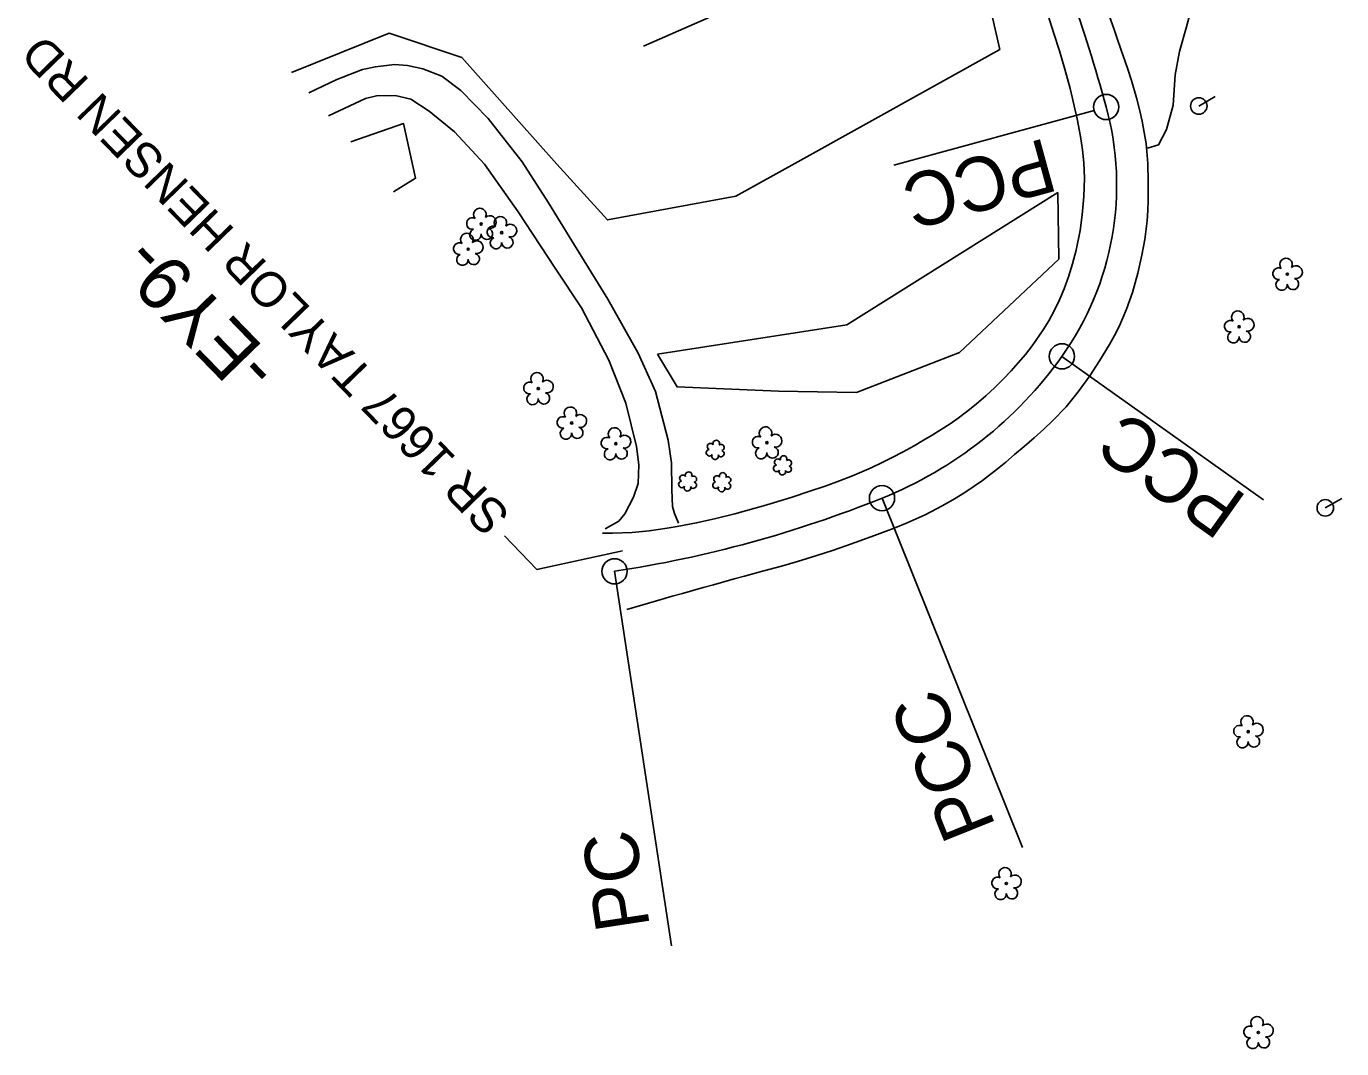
# Model space of a CAD drawing. Extents: x 473158 to 477500, y 500738 to 505114.
# Drawn here: x 475161.7 to 475552.3, y 502010.9 to 502314.3 of the extents above; entities that cross this region are included whole.
import ezdxf

# ---------------------------------------------------------------- set-up
doc = ezdxf.new("R2010")
doc.units = 0
for name, color, linetype in [('Exist Horizontal Alignment', 7, 'Continuous'), ('Exist Horizontal Alignment Direction Label', 7, 'Continuous'), ('Exist Roads EOP', 7, 'Continuous'), ('Exist Roads EOP Leader', 7, 'Continuous'), ('Exist Roads EOP Text', 7, 'Continuous'), ('Exist Roads Soil', 7, 'Continuous'), ('Exist Utilities Power Pole CELL', 7, 'Continuous'), ('Exist Vegetation Shrub CELL', 7, 'Continuous'), ('Exist Vegetation Tree CELL', 7, 'Continuous'), ('Exist Vegetation Woods Line', 7, 'Continuous')]:
    doc.layers.add(name, color=color, linetype=linetype)

msp = doc.modelspace()

# ---------------------------------------------------------------- linework, layer by layer
at = {"layer": 'Exist Horizontal Alignment'}
for p, q in [((475454.89, 502356.7), (475344.98, 502308.44)), ((475478.74, 502289.39), (475419.35, 502273.12)), ((475529.02, 502173.8), (475469.22, 502216.37)), ((475457.54, 502070.57), (475415.8, 502174.28)), ((475353.33, 502041.37), (475336.39, 502152.56))]:
    msp.add_line(p, q, dxfattribs=at)
for centre in [(475482.35, 502290.39), (475469.22, 502216.37), (475415.8, 502174.28), (475336.39, 502152.56)]:
    msp.add_circle(centre, 3.75, dxfattribs=at)
for centre, radius, start, end in [((475007.6, 502160.31), 492.25, 15.3225, 23.7048), ((475397.79, 502267.22), 87.68, 324.5533, 15.3225), ((475370.61, 502286.57), 121.05, 291.9237, 324.5533), ((475282.71, 502504.97), 356.47, 278.6615, 291.9237)]:
    msp.add_arc(centre, radius, start, end, dxfattribs=at)
at = {"layer": 'Exist Roads EOP'}
for points in [[(475332.79, 502163.87), (475335.79, 502163.86), (475341.59, 502164.06), (475346.7, 502164.55), (475351.96, 502165.34), (475354.93, 502165.84), (475360.73, 502166.92), (475366.45, 502168.2), (475372.12, 502169.6), (475377.76, 502171.18), (475380.66, 502172.03), (475383.62, 502172.9), (475389.12, 502174.6), (475394.08, 502176.22), (475398.91, 502177.87), (475403.19, 502179.42), (475407.05, 502180.92), (475412.54, 502183.27), (475415.86, 502184.85), (475418.85, 502186.37), (475422.04, 502188.02), (475425.3, 502189.83), (475428.1, 502191.47), (475430.66, 502192.99), (475433.36, 502194.64), (475436.03, 502196.38), (475438.45, 502198.07), (475440.9, 502199.92), (475443.73, 502202.2), (475446.59, 502204.66), (475449.25, 502207.14), (475451.76, 502209.63), (475454.16, 502212.09), (475456.26, 502214.45), (475458.35, 502216.94), (475460.38, 502219.51), (475463.68, 502224.27), (475465.31, 502226.94), (475466.93, 502229.86), (475468.5, 502233.13), (475469.87, 502236.43), (475471.15, 502239.99), (475472.35, 502243.79), (475473.46, 502247.92), (475474.62, 502253.73), (475475.27, 502258.35), (475475.73, 502263.83), (475475.89, 502269.28), (475475.73, 502273.83), (475475.35, 502277.69), (475474.76, 502281.61), (475473.73, 502286.84), (475473.07, 502289.82), (475472.36, 502292.89), (475471.62, 502295.87), (475470.09, 502301.58), (475468.48, 502307.06), (475466.86, 502312.17), (475465.09, 502317.5)], [(475483.2, 502317.55), (475484.78, 502313.06), (475485.51, 502310.98), (475486.82, 502307.23), (475488.68, 502301.86), (475489.91, 502298.21), (475491.39, 502293.07), (475492.26, 502289.66), (475493.03, 502286.2), (475493.68, 502282.8), (475494.18, 502279.58), (475494.71, 502273.62), (475494.86, 502268.2), (475494.83, 502262.63), (475494.72, 502259.63), (475494.51, 502256.57), (475493.81, 502251.03), (475492.93, 502246.42), (475491.79, 502241.07), (475490.21, 502235.31), (475488.43, 502230.34), (475486.24, 502225.22), (475484.87, 502222.55), (475483.35, 502219.9), (475480.39, 502215.07), (475477.48, 502210.59), (475474.03, 502205.79), (475470.5, 502201.39), (475466.43, 502197.19), (475463.83, 502194.78), (475460.95, 502192.21), (475457.99, 502189.63), (475455.18, 502187.21), (475452.54, 502184.97), (475450.09, 502182.96), (475445.59, 502179.51), (475443.13, 502177.81), (475440.09, 502175.81), (475436.82, 502173.79), (475433.68, 502172.01), (475428.6, 502169.35), (475423.31, 502166.94), (475419.45, 502165.38), (475414.4, 502163.5), (475409.24, 502161.65), (475405.07, 502160.16), (475401.06, 502158.78), (475396.4, 502157.23), (475390.68, 502155.43), (475385.93, 502154.14), (475380.31, 502152.62), (475374.95, 502151.14), (475371.93, 502150.29), (475368.88, 502149.45), (475365.81, 502148.59), (475362.7, 502147.72), (475359.6, 502146.86), (475356.53, 502145.99), (475353.49, 502145.14), (475350.49, 502144.28), (475344.8, 502142.65), (475339.99, 502141.25)]]:
    msp.add_lwpolyline(points, dxfattribs=at)
at = {"layer": 'Exist Roads EOP Leader'}
msp.add_lwpolyline([(475338.72, 502158.6), (475313.34, 502153.09), (475303.69, 502163.12)], dxfattribs=at)
at = {"layer": 'Exist Roads Soil'}
for points in [[(475476.71, 502335.29), (475479.28, 502331.91), (475481.59, 502329.05), (475482.85, 502327.84), (475484.2, 502327.08), (475485.85, 502326.42), (475487.62, 502326.45), (475489.07, 502326.88), (475490.2, 502327.82), (475492.83, 502331.2), (475496.1, 502339.6), (475499.62, 502353.76), (475501.41, 502361.15), (475505.61, 502359.29), (475517.48, 502352.5), (475509.78, 502327.56), (475506.16, 502314.15), (475504.1, 502306.86), (475502.79, 502299.95), (475502.25, 502290.94), (475500.28, 502283.72), (475497.91, 502279.11), (475494.63, 502278.17)], [(475245.62, 502294.54), (475253.91, 502298.54), (475261.56, 502301.52), (475265.37, 502302.33), (475271.04, 502303.02), (475274.91, 502302.7), (475279.45, 502301.76), (475285.13, 502299.53), (475290.73, 502295.29), (475298.89, 502286.99), (475308.91, 502274.13), (475316.82, 502261.92), (475323.71, 502250.62), (475334.41, 502233.33), (475343.36, 502217.32), (475348.51, 502205.92), (475352.34, 502191.52), (475353.34, 502184.79), (475353.41, 502176.78), (475353.55, 502171.85), (475354.23, 502169.75), (475355.41, 502166.83)], [(475333.61, 502165.19), (475337.62, 502167.46), (475339.47, 502169.6), (475342.04, 502174.55), (475343.44, 502178.62), (475343.62, 502184.14), (475342.86, 502189.63), (475339.78, 502202.51), (475334.66, 502215.27), (475326.59, 502230.78), (475318.74, 502242.58), (475307.79, 502259.31), (475297.81, 502273.37), (475288.87, 502283.03), (475281.38, 502289.18), (475275.92, 502292.75), (475271.26, 502293.79), (475265.75, 502293.66), (475262.4, 502292.9), (475251.42, 502287.78)]]:
    msp.add_lwpolyline(points, dxfattribs=at)
at = {"layer": 'Exist Utilities Power Pole CELL'}
for p, q in [((475509.85, 502290.67), (475514.73, 502293.48)), ((475509.85, 502290.67), (475509.85, 502290.67)), ((475547.4, 502171.39), (475552.28, 502174.2)), ((475547.4, 502171.39), (475547.4, 502171.39))]:
    msp.add_line(p, q, dxfattribs=at)
for centre in [(475509.85, 502290.67), (475547.4, 502171.39)]:
    msp.add_circle(centre, 2.45, dxfattribs=at)
at = {"layer": 'Exist Vegetation Shrub CELL'}
for p, q in [((475366.36, 502188.43), (475366.36, 502188.43)), ((475386.33, 502183.84), (475386.33, 502183.84)), ((475358.16, 502179.05), (475358.16, 502179.05)), ((475368.29, 502178.83), (475368.29, 502178.83))]:
    msp.add_line(p, q, dxfattribs=at)
for centre, radius, start, end in [((475364.88, 502189.56), 0.968, 35.8908, 245.4216), ((475366.59, 502190.48), 0.99, 334.8391, 200.4717), ((475368.03, 502189.3), 0.929, 284.4567, 126.0861), ((475364.56, 502187.73), 0.955, 95.1099, 327.9534), ((475366.23, 502186.75), 0.984, 151.2797, 21.387), ((475368, 502187.51), 0.937, 204.9913, 73.4601), ((475384.85, 502184.97), 0.968, 35.8908, 245.4216), ((475386.56, 502185.88), 0.99, 334.8391, 200.4717), ((475388, 502184.71), 0.929, 284.4567, 126.0861), ((475358.38, 502181.09), 0.99, 334.8391, 200.4717), ((475368.52, 502180.87), 0.99, 334.8391, 200.4717), ((475384.53, 502183.14), 0.955, 95.1099, 327.9534), ((475386.2, 502182.16), 0.984, 151.2797, 21.387), ((475387.97, 502182.92), 0.937, 204.9913, 73.4601), ((475356.36, 502178.34), 0.955, 95.1099, 327.9534), ((475356.67, 502180.17), 0.968, 35.8908, 245.4216), ((475358.03, 502177.36), 0.984, 151.2797, 21.387), ((475359.79, 502178.12), 0.937, 204.9913, 73.4601), ((475359.83, 502179.91), 0.929, 284.4567, 126.0861), ((475366.49, 502178.13), 0.955, 95.1099, 327.9534), ((475366.81, 502179.96), 0.968, 35.8908, 245.4216), ((475368.17, 502177.15), 0.984, 151.2797, 21.387), ((475369.93, 502177.9), 0.937, 204.9913, 73.4601), ((475369.97, 502179.7), 0.929, 284.4567, 126.0861)]:
    msp.add_arc(centre, radius, start, end, dxfattribs=at)
at = {"layer": 'Exist Vegetation Tree CELL'}
for p, q in [((475296.8, 502255.64), (475296.8, 502255.64)), ((475302.9, 502253.11), (475302.9, 502253.11)), ((475292.92, 502248.19), (475292.92, 502248.19)), ((475536.15, 502240.77), (475536.15, 502240.77)), ((475521.82, 502225.15), (475521.82, 502225.15)), ((475313.75, 502206.81), (475313.75, 502206.81)), ((475323.66, 502196.59), (475323.66, 502196.59)), ((475336.78, 502190.46), (475336.78, 502190.46)), ((475381.62, 502190.74), (475381.62, 502190.74)), ((475524.53, 502104.97), (475524.53, 502104.97)), ((475452.71, 502059.91), (475452.71, 502059.91)), ((475527.53, 502015.68), (475527.53, 502015.68))]:
    msp.add_line(p, q, dxfattribs=at)
for centre in [(475296.8, 502255.64), (475302.9, 502253.11), (475292.92, 502248.19), (475536.15, 502240.77), (475521.82, 502225.15), (475313.75, 502206.81), (475323.66, 502196.59), (475336.78, 502190.46), (475381.62, 502190.74), (475524.53, 502104.97), (475452.71, 502059.91), (475527.53, 502015.68)]:
    msp.add_circle(centre, 0.326, dxfattribs=at)
for centre, radius, start, end in [((475296.41, 502258.51), 1.86, 330.1651, 219.7134), ((475294.19, 502255.79), 1.73, 62.6636, 279.3457), ((475299.35, 502256.22), 1.9, 257.1011, 134.1999), ((475302.51, 502255.98), 1.86, 330.1651, 219.7134), ((475292.54, 502251.06), 1.86, 330.1651, 219.7134), ((475295.09, 502252.52), 1.69, 111.5671, 6.231), ((475298.47, 502252.74), 1.7, 181.2822, 74.56), ((475300.29, 502253.26), 1.73, 62.6636, 279.3457), ((475304.57, 502250.21), 1.7, 181.2822, 74.56), ((475305.45, 502253.69), 1.9, 257.1011, 134.1999), ((475290.31, 502248.34), 1.73, 62.6636, 279.3457), ((475295.47, 502248.77), 1.9, 257.1011, 134.1999), ((475301.19, 502249.98), 1.69, 111.5671, 6.231), ((475291.22, 502245.06), 1.69, 111.5671, 6.231), ((475294.59, 502245.29), 1.7, 181.2822, 74.56), ((475535.77, 502243.64), 1.86, 330.1651, 219.7134), ((475533.55, 502240.92), 1.73, 62.6636, 279.3457), ((475538.7, 502241.36), 1.9, 257.1011, 134.1999), ((475534.45, 502237.65), 1.69, 111.5671, 6.231), ((475537.82, 502237.87), 1.7, 181.2822, 74.56), ((475521.44, 502228.02), 1.86, 330.1651, 219.7134), ((475519.22, 502225.31), 1.73, 62.6636, 279.3457), ((475524.37, 502225.74), 1.9, 257.1011, 134.1999), ((475520.12, 502222.03), 1.69, 111.5671, 6.231), ((475523.5, 502222.25), 1.7, 181.2822, 74.56), ((475313.36, 502209.68), 1.86, 330.1651, 219.7134), ((475316.3, 502207.39), 1.9, 257.1011, 134.1999), ((475311.14, 502206.96), 1.73, 62.6636, 279.3457), ((475312.05, 502203.69), 1.69, 111.5671, 6.231), ((475315.42, 502203.91), 1.7, 181.2822, 74.56), ((475323.28, 502199.47), 1.86, 330.1651, 219.7134), ((475321.06, 502196.75), 1.73, 62.6636, 279.3457), ((475326.21, 502197.18), 1.9, 257.1011, 134.1999), ((475321.96, 502193.47), 1.69, 111.5671, 6.231), ((475325.33, 502193.69), 1.7, 181.2822, 74.56), ((475336.39, 502193.34), 1.86, 330.1651, 219.7134), ((475381.23, 502193.61), 1.86, 330.1651, 219.7134), ((475384.17, 502191.33), 1.9, 257.1011, 134.1999), ((475334.17, 502190.62), 1.73, 62.6636, 279.3457), ((475338.45, 502187.56), 1.7, 181.2822, 74.56), ((475339.33, 502191.05), 1.9, 257.1011, 134.1999), ((475379.01, 502190.89), 1.73, 62.6636, 279.3457), ((475383.29, 502187.84), 1.7, 181.2822, 74.56), ((475335.07, 502187.34), 1.69, 111.5671, 6.231), ((475379.92, 502187.62), 1.69, 111.5671, 6.231), ((475524.15, 502107.84), 1.86, 330.1651, 219.7134), ((475527.08, 502105.56), 1.9, 257.1011, 134.1999), ((475521.93, 502105.12), 1.73, 62.6636, 279.3457), ((475522.83, 502101.85), 1.69, 111.5671, 6.231), ((475526.2, 502102.07), 1.7, 181.2822, 74.56), ((475452.32, 502062.78), 1.86, 330.1651, 219.7134), ((475450.1, 502060.06), 1.73, 62.6636, 279.3457), ((475455.26, 502060.5), 1.9, 257.1011, 134.1999), ((475451, 502056.79), 1.69, 111.5671, 6.231), ((475454.38, 502057.01), 1.7, 181.2822, 74.56), ((475524.93, 502015.84), 1.73, 62.6636, 279.3457), ((475527.15, 502018.55), 1.86, 330.1651, 219.7134), ((475530.08, 502016.27), 1.9, 257.1011, 134.1999), ((475525.83, 502012.56), 1.69, 111.5671, 6.231), ((475529.21, 502012.78), 1.7, 181.2822, 74.56)]:
    msp.add_arc(centre, radius, start, end, dxfattribs=at)
at = {"layer": 'Exist Vegetation Woods Line'}
for points in [[(475398.73, 502449.23), (475442.9, 502342.11), (475450.77, 502307.49), (475390.78, 502274.13), (475372.41, 502263.9), (475334.31, 502256.89), (475319.24, 502273.44), (475291.09, 502305.03), (475269.5, 502312.26), (475240.44, 502300.6)], [(475258.05, 502280.04), (475273.76, 502285.45), (475277.3, 502269.25), (475270.71, 502265.21)], [(475349.12, 502217.01), (475405.32, 502225.73), (475467.96, 502265), (475468.25, 502245.23), (475438.8, 502217.56), (475408.23, 502205.65), (475385.09, 502206.03), (475354.95, 502207.31), (475349.12, 502217.01)]]:
    msp.add_lwpolyline(points, dxfattribs=at)

# ---------------------------------------------------------------- texts
at = {"layer": 'Exist Horizontal Alignment'}
for s, rotation, p in [('PCC', 195.3225, (475464.38, 502281.27)), ('PCC', 144.5533, (475524.7, 502174.51)), ('PCC', 111.9237, (475449.7, 502076.85)), ('PC', 98.6615, (475346.91, 502047.11))]:
    msp.add_text(s, height=16, rotation=rotation, dxfattribs=at).set_placement(p)
at = {"layer": 'Exist Horizontal Alignment Direction Label'}
msp.add_text('-EY9-', height=16, rotation=134.1739, dxfattribs=at).set_placement((475237.43, 502213.86))
at = {"layer": 'Exist Roads EOP Text'}
msp.add_text('SR 1667 TAYLOR HENSEN RD', height=10.4, rotation=134.1739, dxfattribs=at).set_placement((475305.84, 502169.51))

doc.saveas('drawing.dxf')
